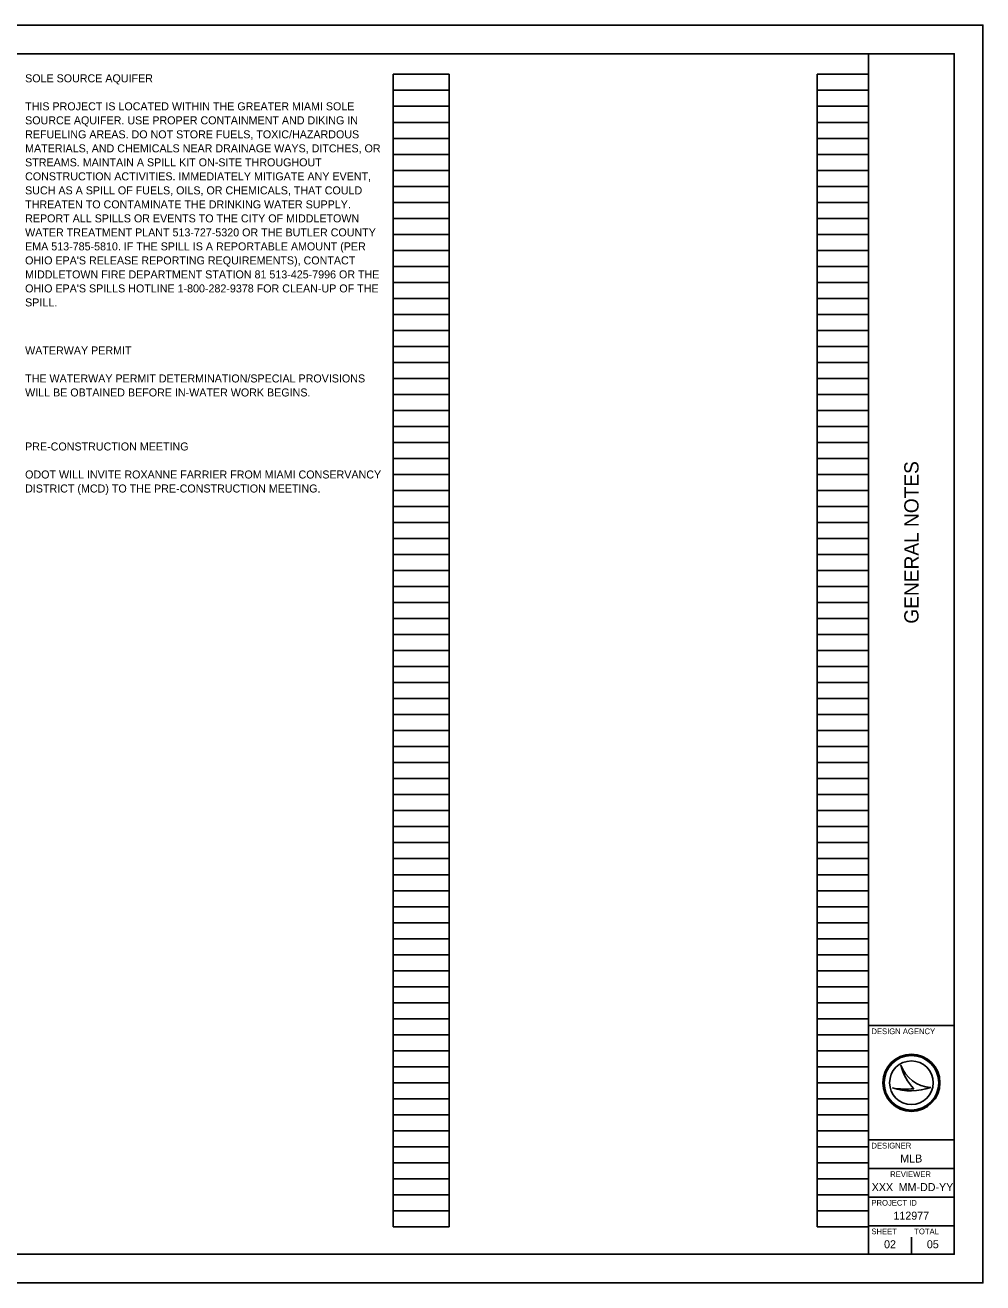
# Model space of a CAD drawing. Extents: x 0 to 34, y 0 to 41.9.
# Drawn here: x 17.24 to 34, y 0 to 22 of the extents above; entities that cross this region are included whole.
import ezdxf

# ---------------------------------------------------------------- set-up
doc = ezdxf.new("R2010")
doc.units = 0
for name, color, linetype in [('SH_Border', 7, 'Continuous'), ('SH_Cut_Line', 7, 'Continuous'), ('SH_Data', 7, 'Continuous'), ('SH_Text', 7, 'Continuous')]:
    doc.layers.add(name, color=color, linetype=linetype)

msp = doc.modelspace()

# ---------------------------------------------------------------- linework, layer by layer
at = {"layer": 'SH_Border'}
for p, q in [((32, 0.5), (32, 21.5)), ((32, 4.5), (33.5, 4.5)), ((32, 2.5), (33.5, 2.5)), ((32, 2), (33.5, 2)), ((32, 1.5), (33.5, 1.5)), ((32, 1), (33.5, 1))]:
    msp.add_line(p, q, dxfattribs=at)
msp.add_lwpolyline([(1.5, 21.5), (33.5, 21.5), (33.5, 0.5), (1.5, 0.5)], close=True, dxfattribs=at)
at = {"layer": 'SH_Cut_Line'}
msp.add_lwpolyline([(0, 0), (34, 0), (34, 22), (0, 22)], close=True, dxfattribs=at)
at = {"layer": 'SH_Data'}
for p, q in [((23.68, 0.98), (23.68, 21.14)), ((23.68, 21.14), (24.66, 21.14)), ((24.66, 0.98), (24.66, 21.14)), ((31.1, 0.98), (31.1, 21.14)), ((31.1, 21.14), (32, 21.14)), ((32, 0.98), (32, 21.14)), ((23.68, 20.86), (24.66, 20.86)), ((31.1, 20.86), (32, 20.86)), ((23.68, 20.58), (24.66, 20.58)), ((31.1, 20.58), (32, 20.58)), ((23.68, 20.3), (24.66, 20.3)), ((31.1, 20.3), (32, 20.3)), ((23.68, 20.02), (24.66, 20.02)), ((31.1, 20.02), (32, 20.02)), ((23.68, 19.74), (24.66, 19.74)), ((31.1, 19.74), (32, 19.74)), ((23.68, 19.46), (24.66, 19.46)), ((31.1, 19.46), (32, 19.46)), ((23.68, 19.18), (24.66, 19.18)), ((31.1, 19.18), (32, 19.18)), ((23.68, 18.9), (24.66, 18.9)), ((31.1, 18.9), (32, 18.9)), ((23.68, 18.62), (24.66, 18.62)), ((31.1, 18.62), (32, 18.62)), ((23.68, 18.34), (24.66, 18.34)), ((31.1, 18.34), (32, 18.34)), ((23.68, 18.06), (24.66, 18.06)), ((31.1, 18.06), (32, 18.06)), ((23.68, 17.78), (24.66, 17.78)), ((31.1, 17.78), (32, 17.78)), ((23.68, 17.5), (24.66, 17.5)), ((31.1, 17.5), (32, 17.5)), ((23.68, 17.22), (24.66, 17.22)), ((31.1, 17.22), (32, 17.22)), ((23.68, 16.94), (24.66, 16.94)), ((31.1, 16.94), (32, 16.94)), ((23.68, 16.66), (24.66, 16.66)), ((31.1, 16.66), (32, 16.66)), ((23.68, 16.38), (24.66, 16.38)), ((31.1, 16.38), (32, 16.38)), ((23.68, 16.1), (24.66, 16.1)), ((31.1, 16.1), (32, 16.1)), ((23.68, 15.82), (24.66, 15.82)), ((31.1, 15.82), (32, 15.82)), ((23.68, 15.54), (24.66, 15.54)), ((31.1, 15.54), (32, 15.54)), ((23.68, 15.26), (24.66, 15.26)), ((31.1, 15.26), (32, 15.26)), ((23.68, 14.98), (24.66, 14.98)), ((31.1, 14.98), (32, 14.98)), ((23.68, 14.7), (24.66, 14.7)), ((31.1, 14.7), (32, 14.7)), ((23.68, 14.42), (24.66, 14.42)), ((31.1, 14.42), (32, 14.42)), ((23.68, 14.14), (24.66, 14.14)), ((31.1, 14.14), (32, 14.14)), ((23.68, 13.86), (24.66, 13.86)), ((31.1, 13.86), (32, 13.86)), ((23.68, 13.58), (24.66, 13.58)), ((31.1, 13.58), (32, 13.58)), ((23.68, 13.3), (24.66, 13.3)), ((31.1, 13.3), (32, 13.3)), ((23.68, 13.02), (24.66, 13.02)), ((31.1, 13.02), (32, 13.02)), ((23.68, 12.74), (24.66, 12.74)), ((31.1, 12.74), (32, 12.74)), ((23.68, 12.46), (24.66, 12.46)), ((31.1, 12.46), (32, 12.46)), ((23.68, 12.18), (24.66, 12.18)), ((31.1, 12.18), (32, 12.18)), ((23.68, 11.9), (24.66, 11.9)), ((31.1, 11.9), (32, 11.9)), ((23.68, 11.62), (24.66, 11.62)), ((31.1, 11.62), (32, 11.62)), ((23.68, 11.34), (24.66, 11.34)), ((31.1, 11.34), (32, 11.34)), ((23.68, 11.06), (24.66, 11.06)), ((31.1, 11.06), (32, 11.06)), ((23.68, 10.78), (24.66, 10.78)), ((31.1, 10.78), (32, 10.78)), ((23.68, 10.5), (24.66, 10.5)), ((31.1, 10.5), (32, 10.5)), ((23.68, 10.22), (24.66, 10.22)), ((31.1, 10.22), (32, 10.22)), ((23.68, 9.94), (24.66, 9.94)), ((31.1, 9.94), (32, 9.94)), ((23.68, 9.66), (24.66, 9.66)), ((31.1, 9.66), (32, 9.66)), ((23.68, 9.38), (24.66, 9.38)), ((31.1, 9.38), (32, 9.38)), ((23.68, 9.1), (24.66, 9.1)), ((31.1, 9.1), (32, 9.1)), ((23.68, 8.82), (24.66, 8.82)), ((31.1, 8.82), (32, 8.82)), ((23.68, 8.54), (24.66, 8.54)), ((31.1, 8.54), (32, 8.54)), ((23.68, 8.26), (24.66, 8.26)), ((31.1, 8.26), (32, 8.26)), ((23.68, 7.98), (24.66, 7.98)), ((31.1, 7.98), (32, 7.98)), ((23.68, 7.7), (24.66, 7.7)), ((31.1, 7.7), (32, 7.7)), ((23.68, 7.42), (24.66, 7.42)), ((31.1, 7.42), (32, 7.42)), ((23.68, 7.14), (24.66, 7.14)), ((31.1, 7.14), (32, 7.14)), ((23.68, 6.86), (24.66, 6.86)), ((31.1, 6.86), (32, 6.86)), ((23.68, 6.58), (24.66, 6.58)), ((31.1, 6.58), (32, 6.58)), ((23.68, 6.3), (24.66, 6.3)), ((31.1, 6.3), (32, 6.3)), ((23.68, 6.02), (24.66, 6.02)), ((31.1, 6.02), (32, 6.02)), ((23.68, 5.74), (24.66, 5.74)), ((31.1, 5.74), (32, 5.74)), ((23.68, 5.46), (24.66, 5.46)), ((31.1, 5.46), (32, 5.46)), ((23.68, 5.18), (24.66, 5.18)), ((31.1, 5.18), (32, 5.18)), ((23.68, 4.9), (24.66, 4.9)), ((31.1, 4.9), (32, 4.9)), ((23.68, 4.62), (24.66, 4.62)), ((31.1, 4.62), (32, 4.62)), ((23.68, 4.34), (24.66, 4.34)), ((31.1, 4.34), (32, 4.34)), ((23.68, 4.06), (24.66, 4.06)), ((31.1, 4.06), (32, 4.06)), ((23.68, 3.78), (24.66, 3.78)), ((31.1, 3.78), (32, 3.78)), ((32.567, 3.81), (32.567, 3.81)), ((23.68, 3.5), (24.66, 3.5)), ((31.1, 3.5), (32, 3.5)), ((32.417, 3.41), (32.417, 3.41)), ((32.75, 3.5), (32.75, 3.5)), ((33.087, 3.419), (33.087, 3.419)), ((23.68, 3.22), (24.66, 3.22)), ((31.1, 3.22), (32, 3.22)), ((23.68, 2.94), (24.66, 2.94)), ((31.1, 2.94), (32, 2.94)), ((23.68, 2.66), (24.66, 2.66)), ((31.1, 2.66), (32, 2.66)), ((23.68, 2.38), (24.66, 2.38)), ((31.1, 2.38), (32, 2.38)), ((23.68, 2.1), (24.66, 2.1)), ((31.1, 2.1), (32, 2.1)), ((23.68, 1.82), (24.66, 1.82)), ((31.1, 1.82), (32, 1.82)), ((23.68, 1.54), (24.66, 1.54)), ((31.1, 1.54), (32, 1.54)), ((23.68, 1.26), (24.66, 1.26)), ((31.1, 1.26), (32, 1.26)), ((23.68, 0.98), (24.66, 0.98)), ((31.1, 0.98), (32, 0.98)), ((32.375, 0.675), (32.375, 0.675)), ((32.75, 0.5), (32.75, 0.8))]:
    msp.add_line(p, q, dxfattribs=at)
for radius in [0.5, 0.477, 0.477, 0.382]:
    msp.add_circle((32.75, 3.5), radius, dxfattribs=at)
for centre, radius, start, end in [((33.116, 3.998), 0.58, 198.9257, 198.9319), ((33.347, 3.97), 0.796, 191.6379, 191.6421), ((33.116, 3.998), 0.58, 198.9319, 267.1657), ((33.347, 3.97), 0.796, 191.6421, 226.0947), ((32.739, 4.37), 1.013, 251.4576, 290.0832), ((32.648, 4.654), 1.266, 259.4964, 259.4995), ((32.739, 4.37), 1.013, 251.4527, 251.4576), ((32.648, 4.654), 1.266, 259.4995, 276.6672)]:
    msp.add_arc(centre, radius, start, end, dxfattribs=at)

# ---------------------------------------------------------------- texts
msp.add_text('GENERAL NOTES', height=0.25, rotation=90, dxfattribs=at).set_placement((32.875, 11.531))
for s, height, p in [('DESIGN AGENCY', 0.1, (32.05, 4.35)), ('DESIGNER', 0.1, (32.05, 2.35)), ('MLB', 0.14, (32.554, 2.105)), ('REVIEWER', 0.1, (32.378, 1.85)), ('XXX', 0.14, (32.055, 1.605)), ('MM-DD-YY', 0.14, (32.526, 1.605)), ('PROJECT ID', 0.1, (32.05, 1.35)), ('112977', 0.14, (32.435, 1.105)), ('SHEET', 0.1, (32.05, 0.85)), ('TOTAL', 0.1, (32.8, 0.85)), ('02', 0.14, (32.271, 0.605)), ('05', 0.14, (33.02, 0.605))]:
    msp.add_text(s, height=height, dxfattribs=at).set_placement(p)
at = {"layer": 'SH_Text'}
for s, p in [('SOLE SOURCE AQUIFER', (17.24, 21)), ('THIS PROJECT IS LOCATED WITHIN THE GREATER MIAMI SOLE ', (17.24, 20.51)), ('SOURCE AQUIFER. USE PROPER CONTAINMENT AND DIKING IN ', (17.24, 20.265)), ('REFUELING AREAS. DO NOT STORE FUELS, TOXIC/HAZARDOUS ', (17.24, 20.02)), ('MATERIALS, AND CHEMICALS NEAR DRAINAGE WAYS, DITCHES, OR ', (17.24, 19.775)), ('STREAMS. MAINTAIN A SPILL KIT ON-SITE THROUGHOUT ', (17.24, 19.53)), ('CONSTRUCTION ACTIVITIES. IMMEDIATELY MITIGATE ANY EVENT, ', (17.24, 19.285)), ('SUCH AS A SPILL OF FUELS, OILS, OR CHEMICALS, THAT COULD ', (17.24, 19.04)), ('THREATEN TO CONTAMINATE THE DRINKING WATER SUPPLY. ', (17.24, 18.795)), ('REPORT ALL SPILLS OR EVENTS TO THE CITY OF MIDDLETOWN ', (17.24, 18.55)), ('WATER TREATMENT PLANT 513-727-5320 OR THE BUTLER COUNTY ', (17.24, 18.305)), ('EMA 513-785-5810. IF THE SPILL IS A REPORTABLE AMOUNT (PER ', (17.24, 18.06)), ("OHIO EPA'S RELEASE REPORTING REQUIREMENTS), CONTACT ", (17.24, 17.815)), ('MIDDLETOWN FIRE DEPARTMENT STATION 81 513-425-7996 OR THE ', (17.24, 17.57)), ("OHIO EPA'S SPILLS HOTLINE 1-800-282-9378 FOR CLEAN-UP OF THE ", (17.24, 17.325)), ('SPILL.', (17.24, 17.08)), ('WATERWAY PERMIT', (17.24, 16.24)), ('THE WATERWAY PERMIT DETERMINATION/SPECIAL PROVISIONS ', (17.24, 15.75)), ('WILL BE OBTAINED BEFORE IN-WATER WORK BEGINS.', (17.24, 15.505)), ('PRE-CONSTRUCTION MEETING', (17.24, 14.56)), ('ODOT WILL INVITE ROXANNE FARRIER FROM MIAMI CONSERVANCY ', (17.24, 14.07)), ('DISTRICT (MCD) TO THE PRE-CONSTRUCTION MEETING.', (17.24, 13.825))]:
    msp.add_text(s, height=0.14, dxfattribs=at).set_placement(p)

doc.saveas('drawing.dxf')
